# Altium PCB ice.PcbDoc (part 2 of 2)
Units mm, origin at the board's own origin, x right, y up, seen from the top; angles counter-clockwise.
Board outline 65 x 30 mm, 4 copper layers (L1 [TOP], L2 [GND], L3[PWR], L4 [BOTTOM]), stack 1.49 mm thick; 140 components, 110 nets, 478 pads, 226 vias.
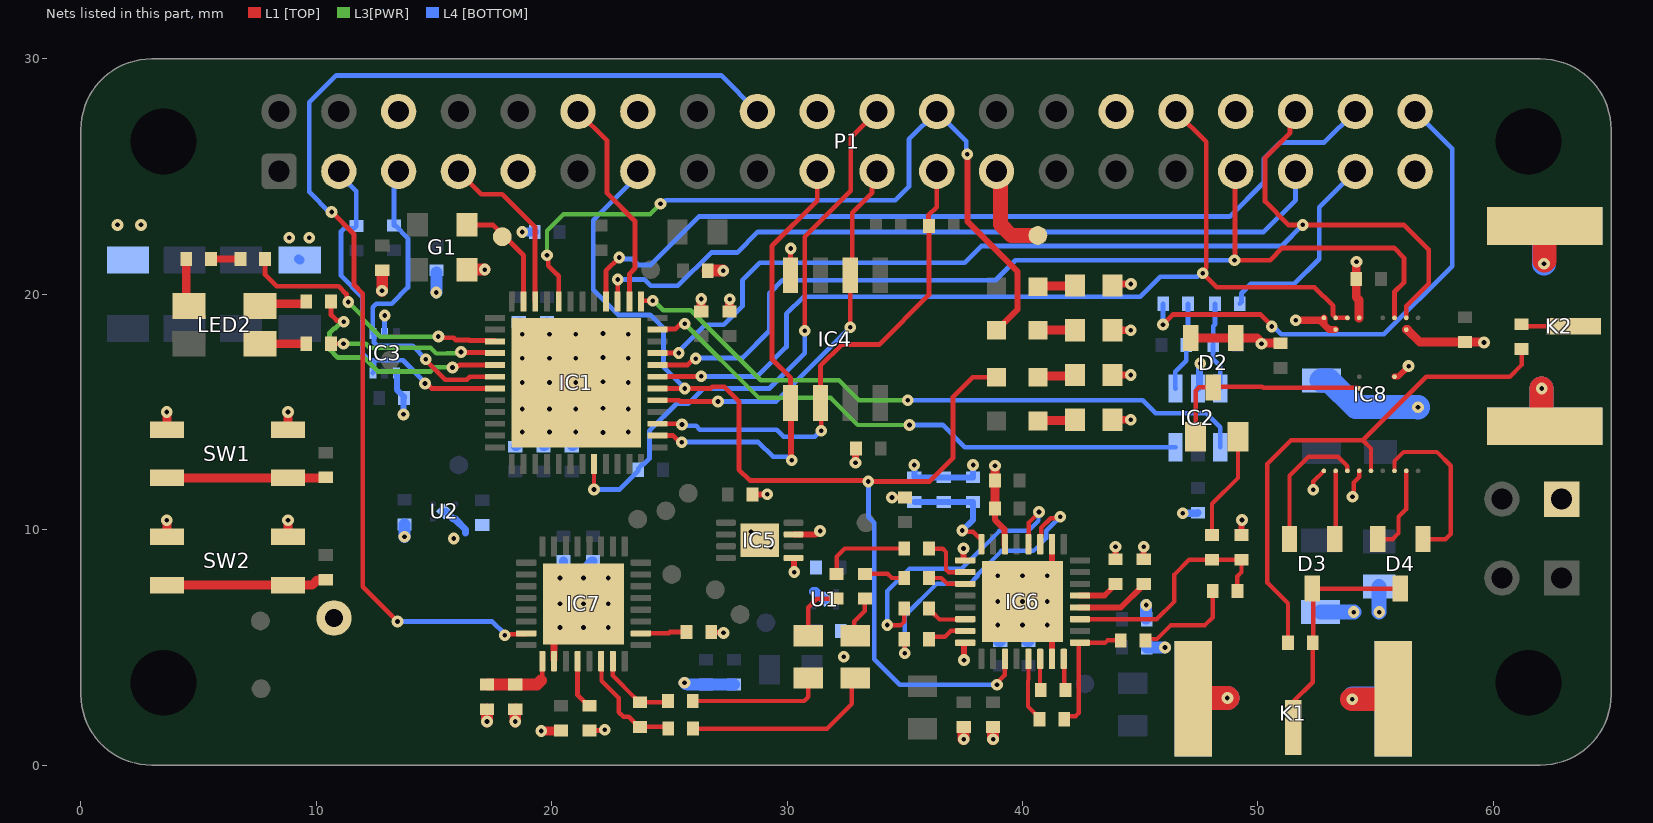
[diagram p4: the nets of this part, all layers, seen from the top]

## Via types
v1: diameter 0.5, hole 0.2, L1 [TOP] to L4 [BOTTOM], tented both sides, 226 vias

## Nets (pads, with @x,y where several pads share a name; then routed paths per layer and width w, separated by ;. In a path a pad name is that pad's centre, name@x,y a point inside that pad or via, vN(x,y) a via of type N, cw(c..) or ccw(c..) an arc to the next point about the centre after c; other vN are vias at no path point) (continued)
F_MISO: IC1.17 IC4.2 P1.21 | length 16.6
  L1 [TOP] w0.203: IC1.17@24.5,15.5 25.416,15.5 25.471,15.445 v1(27.061,15.445) ; v1(32.677,18.597) 32.677,20.75 32.762,20.835 32.762,23.462 33.609,24.309 33.609,25.019 P1.21@33.815,25.225
  L4 [BOTTOM] w0.203: v1(27.061,15.445) 29.525,15.445 v1(32.677,18.597)
F_MOSI: IC1.14 IC4.5 P1.19 | length 22.4
  L1 [TOP] w0.203: IC1.14@24.5,14 25.163,14 25.446,13.717 v1(25.518,13.717) ; IC4.5@30.3,15.8 30.2,15.7 v1(30.2,12.95) 30.2,13.022 30.145,13.077 30.145,16.455 29.357,17.243 29.357,22.057 31.275,23.975 P1.19@31.275,25.225
  L4 [BOTTOM] w0.203: v1(25.518,13.717) 25.526,13.725 28.775,13.725 29.4,13.1 v1@30.2,13.1
F_SCLK: IC1.15 IC4.6 P1.23 R14.2 | length 21.3
  L1 [TOP] w0.203: IC1.15@24.5,14.5 24.505,14.505 25.501,14.505 v1(25.535,14.471) ; v1(31.45,14.2) 31.45,15.353 IC4.6@31.415,15.388 31.415,16.965 32.317,17.867 33.917,17.867 36.025,19.975 36.025,22.75 36,22.775 36,23.35 36.355,23.705 P1.23@36.355,25.225
  L4 [BOTTOM] w0.203: v1(25.535,14.471) 25.592,14.414 26.129,14.414 26.293,14.25 29.55,14.25 29.85,13.95 31.182,13.95 31.432,14.2 v1(31.45,14.2)
GND: C1.1 C2.1 C3.1 C4.1 C5.1 C6.1 C7.1 C8.1 C9.1 C10.1 C11.1 C12.1 C13.1 C14.1 C15.2 C16.2 C17.1 C18.2 C19.1 C20.1 C28.2 C29.2 C30.2 C31.2 C32.2 C33.1 C34.1 C35.2 C36.1 C37.1 C38.1 C39.1 C40.1 C41.1 C42.1 C43.1 C44.1 C45.1 C48.1 C49.1 C50.1 C51.1 C52.1 C53.1 C54.2 C55.2 C56.1 C57.1 C58.1 C59.1 D2.1 D2.2 G1.2 IC1.49 IC2.2 IC3.2 IC3.4 IC4.4 IC5.5 IC5.7 IC5.9 IC6.10 IC6.14 IC6.17 IC6.24 IC6.31 IC6.33 IC7.26 IC7.33 IC8.A1 IC8.A4 IC8.B2 IC8.B8 IC8.F7 IC8.P1 IC8.P4 K1.2 K2.2 K4.1 LED1.1 LED3.1 LED4.1 LED5.1 P1.6 P1.9 P1.14 P1.20 P1.25 P1.30 P1.34 P1.39 R16.2 R24.1 SW1.3 SW1.4 SW2.3 SW2.4 TP20.1 TP27.1 U1.2 U1.5 U2.2 U2.5 | length 95.5
  L1 [TOP] w0.185: v1@8.8,10.35 v1(8.8,10.4) ; v1(52.35,11.7) 52.35,12.05 IC8.P1@52.8,12.5 ; v1(54.019,11.4) 54.066,11.447 54.066,12.007 54.3,12.241 IC8.P4@54.3,12.5
  L1 [TOP] w0.203: R16.2@21.6,1.475 22.225,1.475 v1(22.25,1.5) ; C31.2@26.775,5.65 26.791,5.634 27.284,5.634 v1(27.3,5.618) ; IC4.4@30.145,20.812 30.145,21.845 30.15,21.85 v1(30.15,21.95)
  L1 [TOP] w0.254: C1.1@27.55,19.275 C1.1@27.554,19.279 ; v1@27.554,19.791 v1(27.557,19.795) ; C17.1@28.525,11.5 29.14,11.5 v1(29.15,11.51) ; IC5.5@30.27,8.8 30.292,8.8 30.3,8.792 v1(30.3,8.2) ; IC5.7@30.27,9.8 30.559,9.8 30.563,9.804 31.198,9.804 31.344,9.95 v1(31.4,9.95) ; v1(34.45,11.366) 34.455,11.37 34.995,11.37 C41.1@35,11.375 ; v1(37.494,9.202) 37.494,8.728 37.52,8.703 IC6.17@37.612,8.703 ; v1(37.511,4.461) 37.511,5.172 37.536,5.197 IC6.24@37.612,5.197 ; C39.1@38.824,10.895 38.824,10.426 39.227,10.023 39.227,9.348 IC6.14@39.238,9.338 ; v1@38.825,12.716 v1(38.826,12.717) ; IC6.31@41.245,4.562 41.245,5.705 v1(40,6.95) 41.245,8.195 IC6.10@41.245,9.338 ; C30.2@43.95,8.75 v1(43.95,9.275) ; v1(45.145,9.276) 45.148,9.273 45.148,8.752 C29.2@45.15,8.75 ; C28.2@49.3,9.775 49.3,10.393 v1(49.318,10.411) ; IC8.F7@55.8,16.5 55.95,16.5 v1(56.4,16.95) ; C40.1@38.824,12.095 C40.1@38.825,12.096
  L1 [TOP] w0.3: IC7.26@20.105,4.462 IC7.33@20.105,5.605
  L1 [TOP] w0.305: IC7.33@20.105,5.605 v1(21.35,6.85) ; v1(32.9,12.85) 32.9,13.425 C16.2@32.925,13.45 ; LED5.1@43.825,14.675 v1(44.6,14.675) ; LED4.1@43.825,16.575 v1(44.6,16.575) ; LED3.1@43.825,18.475 v1(44.6,18.475) ; LED1.1@43.825,20.375 43.892,20.442 v1(44.602,20.442) ; v1(51.6,18.9) 52.623,18.9 52.8,18.723 ; IC8.A1@52.8,19 52.8,18.723 ; IC8.B2@53.3,18.5 53.023,18.5 52.8,18.723
  L1 [TOP] w0.381: SW2.3@3.65,9.7 v1(3.65,10.4) ; SW1.3@3.65,14.25 v1(3.65,15) ; SW2.4@8.8,9.7 v1@8.8,10.35 ; SW1.4@8.8,14.25 v1(8.8,15) ; v1(19.55,1.45) 20.375,1.45 C18.2@20.4,1.475 ; C2.1@26.35,19.23 v1(26.35,19.8) ; C1.1@27.554,19.279 v1@27.554,19.791 ; C39.1@38.824,10.895 C40.1@38.824,12.095 v1@38.825,12.716 ; D2.2@47.14,18.15 D2.1@49.06,18.15 49.958,18.15 v1@50.208,17.9 ; v1(50.15,17.9) v1@50.208,17.9 ; C36.1@50.95,17.925 50.275,17.925 50.25,17.9 v1@50.208,17.9 ; v1(54.185,21.383) 54.175,21.372 C32.2@54.175,20.65 54.175,19.875 54.3,19.75 IC8.A4@54.3,19 ; IC8.B8@56.3,18.5 56.35,18.5 56.875,17.975 C35.2@58.8,17.975 59.525,17.975 59.55,17.95 v1(59.6,17.95)
  L1 [TOP] w0.508: v1(12.786,20.149) 12.8,20.163 C56.1@12.8,20.918 ; G1.2@16.4,21.05 v1(17.15,21.05) ; v1(17.25,1.85) C20.1@17.25,2.375 ; v1(18.45,1.85) C19.1@18.45,2.375 ; C9.1@26.625,21 26.629,21.004 v1(27.286,21.004) ; v1(28.465,9.92) IC5.9@28.835,9.55 ; v1(37.5,1.1) C50.1@37.5,1.625 ; v1(38.75,1.1) C51.1@38.75,1.625 ; K1.2@55.725,2.8 K1.2@55.75,2.825 ; K2.2@62.05,14.525 K2.2@62.175,14.4 ; v1(62.15,21.3) 62.15,21.4 v1@62.175,21.425
  L1 [TOP] w0.635: P1.25@38.895,25.225 39.06,25.06 39.06,22.965 39.525,22.5 TP27.1@40.65,22.5
  L1 [TOP] w1.016: K1.2@47.275,2.85 v1(48.7,2.85) ; v1(54,2.8) K1.2@55.725,2.8 ; K2.2@62.05,14.525 v1(62.05,16) ; v1@62.175,21.425 K2.2@62.175,22.9
  L1 [TOP] w1.27: K1.2@47.25,2.825 K1.2@47.275,2.85
  L4 [BOTTOM] w0.203: IC3.2@12.9,18.338 12.902,18.34 v1(12.904,19.096) v1(12.904,19.096) ; C8.1@19.275,22.65 C8.1@19.278,22.647
  L4 [BOTTOM] w0.254: IC3.4@13.4,16.662 13.4,16.575 13.423,16.552 13.423,15.952 13.725,15.65 C15.2@13.725,15.6 13.713,15.587 13.713,14.913 v1(13.7,14.9) ; v1(35.4,12.75) C48.1@35.4,12.225 C49.1@36.65,12.225 R24.1@37.9,12.225 v1(37.9,12.75) ; C53.1@45.25,6.225 C53.1@45.275,6.2 ; C52.1@45.275,5 C52.1@45.277,4.998
  L4 [BOTTOM] w0.305: U2.5@15.425,10.775 15.502,10.775 15.827,10.45 U2.2@15.9,10.45 ; U2.2@15.905,10.45 U2.2@15.9,10.45 ; 16.341,9.87 16.341,10.009 U2.2@15.9,10.45 ; v1(46.8,10.7) 47.425,10.7 C14.1@47.45,10.725 ; IC2.2@47.45,16 47.514,16.064 47.514,17.034 v1(47.544,17.064)
  L4 [BOTTOM] w0.381: C58.1@9.25,21.5 C58.1@9.3,21.45 ; C3.1@18.45,13.525 18.5,13.525 18.559,13.584 18.559,13.938 18.75,14.129 v1(18.75,14.15) ; C6.1@18.6,18.825 18.65,18.825 18.71,18.766 18.71,18.362 18.75,18.321 v1(18.75,18.3) ; v1(18.75,22.65) C8.1@19.275,22.65 ; C4.1@19.65,13.525 19.7,13.525 19.759,13.584 19.759,13.988 19.9,14.129 v1(19.901,14.15) ; v1@19.774,18.3 19.787,18.313 19.787,18.812 C5.1@19.8,18.825 ; v1(20.35,7.95) 20.35,8 20.5,8.15 C42.1@20.5,8.675 ; C7.1@20.85,13.525 20.9,13.525 20.959,13.584 20.959,14.066 21.022,14.129 v1(21.022,14.15) ; v1(21.35,7.95) 21.392,7.992 21.392,8.367 21.7,8.675 C43.1@21.75,8.675 ; U1.2@31.126,7.371 31.206,7.371 31.531,7.046 U1.5@31.601,7.046
  L4 [BOTTOM] w0.508: v1(13.75,9.7) C12.1@13.75,10.225 ; v1(15.096,20.074) 15.098,20.077 15.098,20.928 C57.1@15.1,20.93 ; v1(25.639,3.5) 25.689,3.45 25.75,3.45 25.775,3.425 C33.1@26.55,3.425 C34.1@27.75,3.425 ; v1(38.95,5.95) 39.004,5.896 39.004,5.279 39.008,5.275 C37.1@39.05,5.275 ; v1(40,5.95) 40.204,5.746 40.204,5.279 40.208,5.275 C38.1@40.25,5.275 ; C53.1@45.25,6.225 v1(45.25,6.8) ; C52.1@45.277,4.998 45.279,5 v1(46.05,5) ; v1(54,2.8) v1@54.025,2.825 ; K2.2@62.05,14.525 K2.2@62.175,14.4 ; K2.2@62.15,22.875 K2.2@62.175,22.9
  L4 [BOTTOM] w0.635: C45.1@52.65,6.5 v1(54.071,6.5) ; v1(55.15,6.5) C44.1@55.15,7.595
  L4 [BOTTOM] w1.016: K1.2@47.25,2.825 47.275,2.85 v1(48.7,2.85) ; C55.2@52.7,16.348 53.017,16.348 54.16,15.205 C54.2@55.2,15.205 56.795,15.205 v1(56.8,15.2) ; v1@54.025,2.825 K1.2@55.75,2.825 ; K2.2@62.05,14.525 v1(62.05,16) ; v1(62.15,21.3) K2.2@62.15,22.875
  other v1: 32.4,4.6 20.35,5.85 21.35,5.85 22.4,5.85 41.05,5.95 20.35,6.85 22.4,6.85 38.95,6.95 41.05,6.95 22.4,7.95 38.95,8.05 40,8.05 41.05,8.05 29.3,9.25 15.837,9.627 22.175,14.132 23.25,14.15 18.75,15.128 19.901,15.128 21.022,15.128 23.25,15.128 22.175,15.16 18.75,16.25 19.901,16.25 21.022,16.25 23.25,16.25 22.175,16.282 18.75,17.286 19.901,17.286 21.022,17.286 23.25,17.286 22.175,17.318 19.901,18.3 21.022,18.3 23.25,18.3 22.175,18.332 8.85,22.4 9.7,22.4 1.55,22.95 2.55,22.95
HILO: IC1.18 IC6.27 P1.13 R10.1 | length 48.5
  L1 [TOP] w0.185: P1.13@23.655,24.869 P1.13@23.655,25.225 ; v1(38.914,3.413) 38.914,3.499 39.238,3.823 IC6.27@39.238,4.562
  L1 [TOP] w0.203: IC1.18@24.5,16 v1(25.651,15.999) ; v1@25.65,16.001 25.651,16.003 26.745,16.003 26.814,16.071 27.337,16.071 27.95,15.458 27.95,12.55 28.408,12.092 33.408,12.092 v1(33.45,12.05) 36.05,12.05 37.05,13.05 37.05,15.65 37.875,16.475 R10.1@38.9,16.475
  L4 [BOTTOM] w0.203: P1.13@23.655,25.225 23.655,25.031 21.762,23.137 21.762,20.188 22.825,19.125 24.175,19.125 24.75,18.55 24.75,16.904 25.651,16.003 v1(25.651,15.999) ; v1(33.45,12.05) 33.45,10.55 33.7,10.3 33.7,4.5 34.787,3.413 v1(38.914,3.413)
HV_EN: IC1.34 P1.7 | length 7.4
  L1 [TOP] w0.203: P1.7@16.035,25.225 17.01,24.25 17.9,24.25 19.293,22.857 19.293,19.707 IC1.34@19.3,19.7
ICE_CS: IC1.32 P1.24 R8.1 | length 34.1
  L1 [TOP] w0.203: v1(19.8,21.662) 19.857,21.606 19.857,21.222 20.26,20.818 20.26,20.815 20.3,20.776 IC1.32@20.3,19.7
  L1 [TOP] w0.254: v1(37.65,25.95) 37.652,25.948 37.652,23.098 39.775,20.975 39.775,19.35 R8.1@38.9,18.475
  L3[PWR] w0.185: v1(19.8,21.662) 19.8,22.7 20.5,23.4 24.178,23.4 v1(24.624,23.847)
  L4 [BOTTOM] w0.203: v1(24.624,23.847) 24.699,23.847 24.852,24 34.6,24 35.175,24.575 35.175,26.585 P1.24@36.355,27.765 37.611,26.509 37.611,25.989 v1(37.65,25.95)
Lblue: IC1.41 R5.2 | length 10.3
  L1 [TOP] w0.203: R5.2@10.625,19.7 10.625,19.125 10.858,18.892 11.108,18.892 v1(11.165,18.835) ; v1(15.784,16.891) 15.841,16.948 16.028,16.948 16.082,17.002 17.598,17.002 IC1.41@17.6,17
  L3[PWR] w0.203: v1(11.165,18.835) 11.084,18.835 10.812,18.563 10.764,18.563 10.564,18.364 10.564,17.657 10.907,17.314 12.036,17.314 12.63,16.72 14.848,16.72 15.026,16.898 15.777,16.898 v1(15.784,16.891)
Lgreen: IC1.40 R7.2 | length 7.2
  L1 [TOP] w0.203: R7.2@10.625,17.9 v1(11.15,17.9) ; v1(16.15,17.55) 16.177,17.523 17.577,17.523 IC1.40@17.6,17.5
  L3[PWR] w0.185: v1(11.15,17.9) 12.1,17.9 12.268,17.732 14.855,17.732 15.097,17.489 15.542,17.489 ; 15.543,17.49 16.09,17.49 v1(16.15,17.55)
Lred: IC1.39 R2.2 | length 11.8
  L1 [TOP] w0.203: R2.2@7.825,21.5 7.825,20.831 8.313,20.342 10.946,20.342 11.276,20.012 11.276,19.948 11.306,19.918 11.306,19.723 v1(11.359,19.67) ; v1(15.185,18.209) 15.242,18.153 15.83,18.153 15.923,18.059 16.481,18.059 16.497,18.044 16.975,18.044 16.986,18.033 17.567,18.033 IC1.39@17.6,18
  L3[PWR] w0.185: v1(11.359,19.67) 11.956,19.073 11.956,18.959 12.715,18.2 15.176,18.2 v1(15.185,18.209)
NetC19_2: C19.2 C20.2 IC7.25 | length 3.2
  L1 [TOP] w0.203: 19.55,3.65 19.597,3.697 IC7.25@19.597,4.462
  L1 [TOP] w0.508: C20.2@17.25,3.425 C19.2@18.45,3.425 19.37,3.425 19.55,3.605
NetC21_1: C21.1 IC6.30 | length 1.4
  L1 [TOP] w0.185: C21.1@40.725,3.2 40.744,3.219 40.744,4.544 IC6.30@40.762,4.562
NetC21_2: C21.2 IC6.32 | length 1.4
  L1 [TOP] w0.185: IC6.32@41.753,4.562 41.764,4.551 41.764,3.211 C21.2@41.775,3.2
NetC22_1: C22.1 IC6.1 R17.2 | length 5.5
  L1 [TOP] w0.185: C22.1@41.775,1.95 41.908,2.083 42.252,2.083 42.388,2.218 42.388,5.197 43.505,5.197 43.608,5.3 R17.2@44.175,5.3
NetC22_2: C22.2 IC6.29 | length 2.8
  L1 [TOP] w0.185: IC6.29@40.25,4.515 40.254,4.511 40.254,3.625 40.23,3.601 40.23,2.495 40.725,2 C22.2@40.725,1.95
NetC23_1: C23.1 C25.1 C28.1 IC6.3 | length 10
  L1 [TOP] w0.185: IC6.3@42.395,6.195 45.695,6.195 46.45,6.95 46.45,8.1 47.075,8.725 C25.1@48.05,8.725 49.258,8.725 C28.1@49.3,8.725 49.3,8.2 49.125,8.025 C23.1@49.125,7.4
NetC23_2: C23.2 R17.1 | length 4.4
  L1 [TOP] w0.185: R17.1@45.225,5.3 45.284,5.359 45.709,5.359 46.3,5.95 47.75,5.95 48.075,6.275 C23.2@48.075,7.4
NetC24_1: C24.1 IC7.30 R18.2 | length 4.9
  L1 [TOP] w0.185: IC7.30@22.112,4.462 22.112,3.588 22.85,2.85 22.85,2.25 23.046,2.054 23.271,2.054 23.7,1.625 C24.1@23.75,1.625 24.875,1.625 R18.2@24.95,1.55
NetC24_2: C24.2 IC7.31 R15.2 | length 3.5
  L1 [TOP] w0.185: IC7.31@22.595,4.462 22.595,3.805 23.542,2.858 23.542,2.833 23.7,2.675 C24.2@23.75,2.675 24.89,2.675 R15.2@24.942,2.727
NetC25_2: C25.2 L3.2 | length 4.6
  L1 [TOP] w0.185: C25.2@48.05,9.775 48.05,11.1 49.15,12.2 L3.2@49.15,13.95
NetC26_1: C26.1 L1.1 | length 2.6
  L1 [TOP] w0.185: L1.1@30.9,5.5 30.9,6.7 31.275,7.075 C26.1@32.1,7.075
NetC26_2: C26.2 R19.2 | length 3.7
  L1 [TOP] w0.185: C26.2@32.1,8.125 32.1,8.85 32.45,9.2 R19.2@34.975,9.2
NetC27_1: C27.1 L2.1 | length 1.8
  L1 [TOP] w0.185: L2.1@32.9,5.5 32.85,5.55 32.85,6.1 33.3,6.55 C27.1@33.3,7.075
NetC27_2: C27.2 R20.2 | length 1.7
  L1 [TOP] w0.185: C27.2@33.3,8.125 34.275,8.125 34.45,7.95 R20.2@34.975,7.95
NetC29_1: C29.1 IC6.4 | length 3.1
  L1 [TOP] w0.254: IC6.4@42.388,6.696 44.171,6.696 C29.1@45.1,7.625
NetC30_1: C30.1 IC6.5 | length 1.8
  L1 [TOP] w0.254: IC6.5@42.388,7.204 43.479,7.204 43.95,7.675 C30.1@44,7.675
NetC31_1: C31.1 IC7.2 | length 2
  L1 [TOP] w0.185: IC7.2@23.738,5.605 24.537,5.605 24.543,5.6 24.957,5.6 24.963,5.605 24.98,5.605
  L1 [TOP] w0.203: 24.98,5.605 25.025,5.65 C31.1@25.725,5.65
NetC46_1: C46.1 IC6.11 | length 12.2
  L1 [TOP] w0.185: C46.1@34.975,5.35 35,5.325 v1(35,4.75) ; IC6.11@40.762,9.697 40.788,9.723 40.788,10.08 41.197,10.49 41.54,10.49 v1(41.6,10.55)
  L4 [BOTTOM] w0.185: v1(35,4.75) 35,6.35 36.35,7.7 37.75,7.7 38.1,8.05 38.1,8.1 39.1,9.1 40.461,9.1 41.004,9.643 41.004,9.954 v1(41.6,10.55)
NetC46_2: C46.2 IC6.23 | length 1.7
  L1 [TOP] w0.185: C46.2@36.025,5.45 36.7,5.45 36.955,5.705 IC6.23@37.612,5.705
NetC47_1: C47.1 IC6.12 | length 12.4
  L1 [TOP] w0.185: v1(34.25,5.95) 34.832,5.95 34.968,6.085 34.968,6.643 C47.1@34.975,6.65 ; IC6.12@40.288,9.371 40.268,9.391 40.268,10.306 40.7,10.737 v1(40.7,10.75)
  L4 [BOTTOM] w0.185: v1(34.25,5.95) 34.25,7.4 35.2,8.35 37.416,8.35 39.016,9.95 40.244,9.95 40.679,10.385 40.679,10.729 v1(40.7,10.75)
NetC47_2: C47.2 IC6.22 | length 1.8
  L1 [TOP] w0.185: C47.2@36.025,6.7 36.183,6.542 36.183,6.477 36.472,6.188 IC6.22@37.612,6.188
NetC48_2: C48.2 C49.2 IC6.16 R24.2 | length 5.1
  L1 [TOP] w0.185: v1(37.442,9.966) 37.494,9.913 37.896,9.913 38.157,9.652 38.187,9.652 38.247,9.592 IC6.16@38.247,9.338
  L4 [BOTTOM] w0.254: C48.2@35.4,11.175 C49.2@36.65,11.175 R24.2@37.9,11.175 37.9,10.424 v1(37.442,9.966)
NetD2_3: D2.3 IC8.G4 L3.1 | length 9
  L1 [TOP] w0.185: L3.1@47.35,13.95 47.362,13.963 47.362,15.915 47.498,16.05 D2.3@48.1,16.05 48.125,16.075 50.175,16.075 50.225,16.025 54.209,16.025 54.232,16.003 54.297,16.003 IC8.G4@54.3,16
NetD3_1: D3.1 IC8.P2 | length 2.9
  L1 [TOP] w0.185: D3.1@53.26,9.6 53.3,9.64 IC8.P2@53.3,12.5
NetD3_2: D3.2 IC8.P3 | length 5.9
  L1 [TOP] w0.185: D3.2@51.34,9.6 51.34,12.29 52.15,13.1 53.4,13.1 53.797,12.703 53.797,12.503 IC8.P3@53.8,12.5
NetD3_3: D3.3 D4.3 K1.1 R22.1 | length 10.6
  L1 [TOP] w0.185: K1.1@51.5,1 51.5,2.7 52.325,3.525 R22.1@52.325,5.2 52.35,5.225 52.35,7.45 D3.3@52.3,7.5 D4.3@56.05,7.5
NetD4_1: D4.1 IC8.P7 | length 7.4
  L1 [TOP] w0.185: IC8.P7@55.8,12.5 55.8,12.915 56.185,13.3 57.6,13.3 58.185,12.715 58.185,9.82 57.965,9.6 D4.1@57.01,9.6
NetD4_2: D4.2 IC8.P8 | length 3.8
  L1 [TOP] w0.185: D4.2@55.09,9.6 55.714,9.6 55.97,9.856 55.97,10.548 56.3,10.877 IC8.P8@56.3,12.5
NetIC2_1: IC2.1 R30.2 R31.2 | length 3.6
  L4 [BOTTOM] w0.203: IC2.1@46.5,16 46.49,16.01 46.49,16.719 46.95,17.179 R30.2@46.95,17.65 ; R30.2@46.95,17.85 46.95,18.6 47.025,18.675 R31.2@47.025,19.6
NetIC2_3: IC2.3 R29.2 R32.2 | length 3.8
  L4 [BOTTOM] w0.203: R32.2@48.175,19.6 48.175,18.725 48.1,18.65 R29.2@48.1,17.85 48.084,17.834 48.084,17.266 48.4,16.95 IC2.3@48.4,16
NetIC7_28: IC7.28 R16.1 | length 2.2
  L1 [TOP] w0.185: IC7.28@21.096,4.361 IC7.28@21.096,4.462
  L1 [TOP] w0.203: IC7.28@21.096,4.361 21.096,2.979 21.55,2.525 R16.1@21.6,2.525
NetK2_1: K2.1 R23.2 | length 2.6
  L1 [TOP] w0.185: R23.2@61.2,18.725 61.275,18.65 K2.1@63.75,18.65
NetL1_2: L1.2 R15.1 | length 5.8
  L1 [TOP] w0.185: R15.1@25.992,2.727 30.727,2.727 30.9,2.9 L1.2@30.9,3.7
NetL2_2: L2.2 R18.1 | length 8.3
  L1 [TOP] w0.185: R18.1@26,1.55 31.693,1.55 32.75,2.607 32.75,3.55 L2.2@32.9,3.7
NetLED1_2: LED1.2 R4.2 | length 1.6
  L1 [TOP] w0.381: R4.2@40.65,20.325 40.675,20.35 42.2,20.35 LED1.2@42.225,20.375
NetLED2_1: LED2.1 R1.1 | length 2.1
  L1 [TOP] w0.381: R1.1@4.475,21.5 4.475,19.625 LED2.1@4.6,19.5
NetLED2_3: LED2.3 R5.1 | length 2.1
  L1 [TOP] w0.381: LED2.3@7.6,19.5 7.7,19.6 9.516,19.6 9.575,19.66 R5.1@9.575,19.7
NetLED2_4: LED2.4 R7.1 | length 2
  L1 [TOP] w0.381: LED2.4@7.6,17.9 R7.1@9.575,17.9
NetLED3_2: LED3.2 R8.2 | length 1.6
  L1 [TOP] w0.381: R8.2@40.65,18.475 LED3.2@42.225,18.475
NetLED4_2: LED4.2 R10.2 | length 1.6
  L1 [TOP] w0.381: R10.2@40.65,16.475 40.7,16.525 42.175,16.525 LED4.2@42.225,16.575
NetLED5_2: LED5.2 R9.2 | length 1.6
  L1 [TOP] w0.381: R9.2@40.65,14.625 40.675,14.65 42.2,14.65 LED5.2@42.225,14.675
NetR1_2: R1.2 R2.1 | length 1.3
  L1 [TOP] w0.305: R1.2@5.525,21.5 R2.1@6.775,21.5
NetR21_1: R21.1 SW2.1 SW2.2 | length 6.8
  L1 [TOP] w0.381: SW2.1@3.65,7.65 SW2.2@8.8,7.65 9.82,7.65 10.045,7.875 R21.1@10.4,7.875
NetR26_1: R26.1 SW1.1 SW1.2 | length 7
  L1 [TOP] w0.381: SW1.1@3.65,12.2 SW1.2@8.8,12.2 ; SW1.2@8.55,12.2 10.375,12.2 R26.1@10.4,12.225
OutRange: IC7.23 P1.18 | length 49.6
  L1 [TOP] w0.185: v1(18,5.514) 18.046,5.56 18.916,5.56 IC7.23@18.962,5.605
  L1 [TOP] w0.203: v1(10.65,23.5) 11.6,22.55 11.6,20.4 11.976,20.024 11.976,7.574 v1(13.45,6.1)
  L4 [BOTTOM] w0.203: v1@10.6,23.45 9.7,24.35 9.7,28.15 10.85,29.3 27.2,29.3 P1.18@28.735,27.765 ; v1(13.45,6.1) 17.474,6.1 18,5.574 v1(18,5.514)
PCM_CLK: IC1.26 P1.12 | length 9.2
  L1 [TOP] w0.203: P1.12@21.115,27.765 22.35,26.53 22.35,24.3 23.537,23.113 23.537,21.107 23.308,20.878 23.308,20.423 23.3,20.415 IC1.26@23.3,19.7
PCM_DIN: IC1.28 P1.38 | length 36.8
  L1 [TOP] w0.203: IC1.28@22.3,19.7 22.3,20.998 v1(22.864,21.562)
  L4 [BOTTOM] w0.203: v1(22.864,21.562) 22.92,21.505 23.409,21.505 23.664,21.25 24.2,21.25 26.25,23.3 48.8,23.3 50.25,24.75 50.25,25.75 50.95,26.45 52.82,26.45 P1.38@54.135,27.765
PCM_FS: IC1.27 P1.35 | length 32.6
  L1 [TOP] w0.185: IC1.27@22.8,19.7 22.802,19.702 22.802,20.629 v1(22.804,20.631)
  L4 [BOTTOM] w0.203: v1(22.804,20.631) 23.933,20.631 24.205,20.36 25.36,20.36 26.775,21.775 27.875,21.775 28.75,22.65 50.25,22.65 51.595,23.995 P1.35@51.595,25.225
Pdamp: IC1.19 IC8.A2 IC8.A3 P1.32 | length 40.4
  L1 [TOP] w0.203: IC1.19@24.5,16.5 24.508,16.508 26.344,16.508 v1(26.352,16.515) ; P1.32@46.515,27.765 47.8,26.48 47.8,21.13 47.65,20.98 v1(47.65,20.9) 48.25,20.3 52.4,20.3 53.192,19.508 53.192,19.112 53.3,19.004 IC8.A2@53.3,19 53.303,19.003 53.368,19.003 53.369,19.004 53.792,19.004 53.796,19 IC8.A3@53.8,19
  L4 [BOTTOM] w0.203: v1(26.352,16.515) 26.362,16.505 28.705,16.505 29.966,17.767 29.966,19.167 30.7,19.9 45,19.9 45.85,20.75 47.425,20.75 47.575,20.9 v1(47.65,20.9)
PHV: IC1.21 IC8.A8 P1.36 | length 45.8
  L1 [TOP] w0.203: IC1.21@24.5,17.5 24.502,17.502 25.398,17.502 v1(25.4,17.504) ; P1.36@51.595,27.765 51.366,27.536 51.366,26.866 50.3,25.8 50.3,23.945 51.295,22.95 v1(51.9,22.95) 56.2,22.95 57.25,21.9 57.25,20.45 56.3,19.5 IC8.A8@56.3,19
  L4 [BOTTOM] w0.203: v1(25.4,17.504) 25.4,17.576 26.527,18.703 27.303,18.703 28.1,19.5 28.1,20.6 28.844,21.344 37.544,21.344 38.25,22.05 51,22.05 v1(51.9,22.95)
PnHV: IC1.20 IC8.A7 P1.33 | length 41.4
  L1 [TOP] w0.203: IC1.20@24.5,17 25.769,17 26.038,17.268 v1(26.118,17.268) ; P1.33@49.055,25.225 49.027,25.198 49.027,21.477 v1(49,21.45) 50.515,21.45 51.035,21.97 55.78,21.97 56.2,21.55 56.2,20.5 55.8,20.1 IC8.A7@55.8,19
  L4 [BOTTOM] w0.203: v1(26.118,17.268) 26.14,17.29 28.09,17.29 29.25,18.45 29.25,20.05 29.8,20.6 38.85,20.6 39.7,21.45 v1(49,21.45)
RCLK: G1.3 IC1.35 TP6.1 | length 4.9
  L1 [TOP] w0.203: G1.3@16.4,22.95 17.5,22.95 18.8,21.65 IC1.35@18.8,19.7
RESET: IC1.8 P1.22 R3.2 | length 24.7
  L1 [TOP] w0.185: v1(21.794,11.709) 21.797,11.712 21.797,12.797 IC1.8@21.8,12.8
  L1 [TOP] w0.203: v1(30.75,18.45) 30.75,22.45 32.7,24.4 32.7,26.65 P1.22@33.815,27.765
  L4 [BOTTOM] w0.203: v1(21.794,11.709) v1(21.794,11.709) 22.885,11.71 23.675,12.5 23.675,12.6 23.833,12.758 23.883,12.758 24.15,13.025 24.15,14.2 25.3,15.35 25.8,15.35 26.45,16 29.25,16 30.75,17.5 v1(30.75,18.45)
SCL: IC1.42 IC3.1 P1.5 R12.2 | length 14.6
  L1 [TOP] w0.203: v1(14.65,17.237) 14.65,17.199 15.478,16.371 16.4,16.371 16.528,16.5 IC1.42@17.6,16.5
  L4 [BOTTOM] w0.203: IC3.1@12.4,18.338 IC3.1@12.4,18.396 ; P1.5@13.495,25.225 13.3,25.03 13.3,23.9 R12.2@13.3,22.925 13.35,22.925 13.892,22.383 13.892,20.292 13.2,19.6 12.549,19.6 12.4,19.451 IC3.1@12.4,18.396 ; v1(14.65,17.237) 14.65,17.25 14.092,17.808 12.589,17.808 12.454,17.943 12.454,18.342 IC3.1@12.4,18.396
SDA: IC1.43 IC3.6 P1.3 R11.2 | length 15.8
  L1 [TOP] w0.203: v1(14.614,16.21) 14.694,16.21 14.904,16 IC1.43@17.6,16
  L4 [BOTTOM] w0.203: P1.3@10.955,25.225 10.955,25.132 11.7,24.387 R11.2@11.7,22.9 11.604,22.804 11.185,22.804 11.05,22.669 11.05,20.794 11.958,19.887 11.958,17.5 12.258,17.2 12.455,17.2 13.682,17.2 14.614,16.268 v1(14.614,16.21) ; IC3.6@12.4,16.662 12.455,16.717 12.455,17.198 12.457,17.2
TOP_T1: IC1.23 IC2.6 | length 24.3
  L1 [TOP] w0.203: IC1.23@24.5,18.5 24.523,18.523 25.25,18.523 25.42,18.693 25.595,18.693 v1(25.652,18.75)
  L3[PWR] w0.185: v1(25.652,18.75) 28.802,15.6 31.85,15.6 33,14.45 v1(35.2,14.45)
  L4 [BOTTOM] w0.203: v1(35.2,14.45) 36.6,14.45 37.55,13.5 IC2.6@46.5,13.5
TOP_T1_in: P1.40 R31.1 | length 22.1
  L1 [TOP] w0.203: v1(45.963,18.713) 46.387,19.137 50.113,19.137 50.589,18.661 v1(50.589,18.631)
  L4 [BOTTOM] w0.185: R31.1@45.963,19.587 R31.1@45.975,19.6
  L4 [BOTTOM] w0.203: v1(45.963,18.713) R31.1@45.963,19.587 ; v1(50.589,18.631) 50.663,18.631 50.995,18.3 55.35,18.3 58.25,21.2 58.25,26.19 P1.40@56.675,27.765
TOP_T2: IC1.25 IC2.4 | length 27.7
  L1 [TOP] w0.203: IC1.25@23.8,19.7 23.828,19.728 v1(24.289,19.728)
  L3[PWR] w0.185: v1(24.289,19.728) 24.333,19.728 24.735,19.326 25.904,19.326 28.881,16.35 32.2,16.35 33.05,15.5 v1(35.122,15.5)
  L4 [BOTTOM] w0.203: v1(35.122,15.5) 45.1,15.5 45.65,14.95 47.804,14.95 48.4,14.354 IC2.4@48.4,13.5
TOP_T2_in: P1.37 R32.1 | length 8.7
  L4 [BOTTOM] w0.203: R32.1@49.225,19.6 49.3,19.675 49.3,20.05 49.7,20.45 51.55,20.45 52.6,21.5 52.6,23.69 P1.37@54.135,25.225
VOH2: IC6.18 R19.1 | length 2.4
  L1 [TOP] w0.185: R19.1@36.025,9.2 36.035,9.19 36.615,9.19 36.75,9.055 36.75,8.302 36.853,8.199 IC6.18@37.565,8.2
VOL2: IC6.19 R20.1 | length 1.7
  L1 [TOP] w0.185: R20.1@36.025,7.95 36.55,7.95 36.788,7.712 IC6.19@37.612,7.712
XDCR: IC8.P5 R22.2 R23.1 | length 22.6
  L1 [TOP] w0.185: R22.2@51.275,5.2 51.275,6.875 50.4,7.75 50.4,12.8 51.4,13.8 54.45,13.8 ; IC8.P5@54.8,12.5 54.8,13.45 54.45,13.8 ; R23.1@61.2,17.675 61.2,17 60.7,16.5 57.15,16.5 54.45,13.8
pads on no net: IC3.3 IC6.6 IC6.8 IC6.9 IC6.20 IC7.7 IC7.8 IC7.9 IC7.10 P1.11 P1.15 P1.17 P1.27 P1.28 P1.31

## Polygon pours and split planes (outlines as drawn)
+3V3_IN on L4 [BOTTOM] "+3V3_IN_L04_P022" (solid, pour order 22): 5.9,21.1 5.9,25.6 6.7,26.4 8.75,26.4 9.35,25.8 9.35,24.25 7.95,22.85 7.95,20.9 7.65,20.6 6.1,20.6 5.9,20.8
+1V2 on L4 [BOTTOM] "+1V2_L04_P036" (solid, pour order 36): 17.4,13.275 17.4,11.75 17.75,11.4 19.5,11.4 20.195,12.095 20.195,12.645 20.45,12.9 21.15,12.9 21.3,12.75 21.3,11.95 20.15,10.8 16.004,10.8 15.3,11.504 15.3,13.275
5VLNA on L4 [BOTTOM] "5VLNA_L04_P014" (solid, pour order 14): 45.25,3 45.213,2.963 42.012,2.963 41.764,3.211 41.764,4.014 42.75,5 42.75,8.5 43,8.75 44.25,8.75 44.75,8.25 44.75,4.75 45.25,4.25
+3V3 on L4 [BOTTOM] "+3V3_L04_P007" (solid, pour order 7): 13.356,11.884 13.39,11.85 14.81,11.85 15.04,11.619 15.04,10.967 13.356,10.967
+1V8 on L4 [BOTTOM] "+1V8_L04_P021" (solid, pour order 21): 30.2,5.25 30.1,5.35 28.65,5.35 28.4,5.6 28.4,6.6 28.65,6.85 31.2,6.85 31.6,6.45 31.6,3.5 31.35,3.25 30.428,3.25 30.201,3.476
+3V3 on L4 [BOTTOM] "+3V3_L04_P006" (solid, pour order 6): 31.75,8.4 31.75,7.421 32.1,7.071 32.1,6.55 32.6,6.55 33,6.95 33,8.45 32.8,8.65 32,8.65
GND on L4 [BOTTOM] "GND_L04_P029" (solid, pour order 29): 17.339,10.466 17.325,10.48 16.175,10.48 16.159,10.496 15.715,10.052 15.339,9.676 15.339,9.316 15.539,9.116 15.939,9.116 16.439,9.616 17.239,9.616 17.499,9.877 17.499,10.357
GND on L4 [BOTTOM] "GND_L04_P035" (solid, pour order 35): 20.05,8.25 22.75,8.25 22.75,5.5 20.05,5.5
GND on L4 [BOTTOM] "GND_L04_P034" (solid, pour order 34): 18.3,18.6 23.65,18.6 23.65,13.671 18.3,13.671
GND on L4 [BOTTOM] "GND_L04_P033" (solid, pour order 33): 8.4,20.8 10.3,20.8 10.3,22.45 9.95,22.8 8.7,22.8 8.4,22.5
GND on L4 [BOTTOM] "GND_L04_P032" (solid, pour order 32): 1.1,20.8 3,20.8 3,23.9 2.8,24.1 1.3,24.1 1.1,23.9
GND on L4 [BOTTOM] "GND_L04_P030" (solid, pour order 30): 32.85,6.05 32.85,4.35 32.7,4.2 32.15,4.2 31.95,4.4 31.95,6.05
GND on L4 [BOTTOM] "GND_L04_P008" (solid, pour order 8): 30,8.65 31.35,8.65 31.45,8.55 31.45,7.37 31.28,7.2 30.15,7.2 30,7.35
+5V_IN on L4 [BOTTOM] "+5V_IN_L04_P016" (solid, pour order 16): 3.5,20.8 5.4,20.8 5.4,23.9 5.2,24.1 3.7,24.1 3.5,23.9
+3V3 on L4 [BOTTOM] "+3V3_L04_P024" (solid, pour order 24): 5.9,19.2 5.9,17.75 6.05,17.6 6.05,15.9 6.3,15.65 8.65,15.65 10.2,15.65 10.45,15.9 10.45,19.1 10.15,19.4 6.05,19.4
+1V8f on L4 [BOTTOM] "+1V8F_L04_P003" (solid, pour order 3): 29.294,5.2 29.694,4.8 29.699,3.399 29.55,3.25 28.6,3.25 28.5,3.35 28.5,3.75 28.25,4 25.95,4 25.75,4.2 25.75,5 25.95,5.2
+5V on L4 [BOTTOM] "+5V_L04_P023" (solid, pour order 23): 43.1,2.15 42.8,1.85 42.8,0.85 43.1,0.55 45.3,0.55 45.3,2.15
GND on L4 [BOTTOM] "GND_L04_P019" (solid, pour order 19): 38.5,8.6 41.65,8.6 41.65,5.3 38.5,5.3
+5V on L4 [BOTTOM] "+5V_L04_P013" (solid, pour order 13): 3.09,15.741 3.25,16.028 3.25,16.59 3.25,16.681 3.25,17.25 3.75,17.75 5.25,17.75 5.5,18 5.5,19.1 5.25,19.35 1.2,19.35 1,19.15 1,16.25 1.509,15.741
+3V3 on L3[PWR] "+3V3_L03_P020" (solid, pour order 20): -0.05,30 -0.05,-0.05 65.05,-0.05 65.05,30
+5V on L3[PWR] "+5V_L03_P015" (solid, pour order 15): 3.45,18.25 3.45,15.9 5.5,13.85 5.5,8.25 9.75,4 46.5,4 49.7,7.2 49.7,19.45 52.25,22 56.25,22 56.5,22 57.5,21 57.5,17 59.25,15.25 63.5,15.25 64.75,14 64.75,8.75 64.75,0 0,0 0,18.25
+5V_IN on L3[PWR] "+5V_IN_L03_P009" (solid, pour order 9): 11.75,29.85 11.7,29.8 -0.05,29.8 -0.05,21.4 0.05,21.3 5.3,21.3 6.15,22.15 6.15,25.55 7.2,26.6 11.95,26.6 12.2,26.85 12.2,29.2
0V9 on L3[PWR] "0V9_L03_P010" (solid, pour order 10): 37.535,3.865 37.535,12.585 38.45,13.5 41.3,13.5 41.9,12.9 41.9,11.75 41.35,11.2 40,11.2 38.5,9.7 38.5,5.4 39,4.9 40.15,4.9 40.744,4.306 40.722,3.722 40.5,3.5 37.9,3.5
+1V8f on L3[PWR] "+1V8F_L03_P004" (solid, pour order 4): 24.8,5.65 25.4,5.65 25.75,5.3 25.75,4.384 25.5,4.134 19.566,4.134 18.75,4.95 18.35,4.95 18.05,4.65 18.05,3.95 18.4,3.6 20.546,3.6 21.471,2.675 26.625,2.675 27.1,3.15 27.1,5.9 26.404,6.596 24.48,6.596 24.48,5.97
5VVGA on L3[PWR] "5VVGA_L03_P005" (solid, pour order 5): 36.25,5.4 35.53,4.68 35.53,3.995 35.69,3.835 36.985,3.835 37.249,4.099 37.249,6.813 36.962,7.101 36.452,7.101 36.25,6.9
5VVGA on L1 [TOP] "5VVGA_L01_P038" (solid, pour order 38): 34.053,4.3 36.785,4.3 37.22,3.865 38.235,3.865 38.5,3.6 38.5,3.3 38.8,3 39,3 39.1,2.9 39.1,2.35 39.05,2.3 36.7,2.3 36.3,2.7 34.1,2.7 33.9,2.9 33.9,4.147
+2V5 on L1 [TOP] "+2V5_L01_P037" (solid, pour order 37): 24.411,20.639 24.25,20.799 24.25,22.849 24.389,22.988 24.797,23.4 26,23.4 26,20.65 25.75,20.4 24.651,20.4
+5V on L1 [TOP] "+5V_L01_P012" (solid, pour order 12): 36.35,2 34.1,2 33.85,1.75 33.85,0.65 34,0.5 36.35,0.5
GND on L2 [GND] "GND_L02_P000" (solid, pour order 0): -0.05,30 -0.05,-0.05 65.05,-0.05 65.05,30

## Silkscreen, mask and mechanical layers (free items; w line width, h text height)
Top Overlay:
  text "Pulser" at 48.15,22.15 h0.8
  text "DONE" at 35.1,19.9 h0.8
  text "ICS" at 35.1,17.9 h0.8
  text "HILO" at 35.1,16.05 h0.8
  text "PWR" at 35.14,14.2 h0.8
  text "VGA" at 35.55,12.375 h0.8
  text "USER" at 2.07,11.53 h1 r90
  text "DAC" at 29.39,11.21 h0.8
  text "FPGA" at 15.19,11.117 h0.8
  text "ADC" at 15.8,7.25 h0.8
  text "TRIG" at 2.07,6.93 h1 r90
  text "GND" at 12.1,5.8 h0.8
  text "+3V3" at 5.9,4.7 h0.8
  text "+5V" at 6.35,1.7 h0.8
Bottom Overlay:
  drawing of 5 lines, arcs and shapes, not listed
  text "lit3-32" at 39.246,20.504 h1.52
  text "un0rick.cc" at 41.496,18.004 h1.52
  text "O" at 9,3.25 h15
  text "FR000016" at 15.6,0.65 h0.95
M2_BoardOutline:
  lines w0.254: 0,27 cw(c3,27) 3,30 ; 0,27 0,27 ; 0,27 0,3 ccw(c3,3) 3,0 ; 3,0 3,0 ; 3,0 62,0 ccw(c62,3) 65,3 ; 3,30 62,30 cw(c62,27) 65,27 65,3 ; 3,30 3,30 ; 65,3 65,3
M5_StackDetails:
  drawing of 453 lines, arcs and shapes, not listed
  text "Layer" at -21.908,126.177 h1.52
  text "Name" at -11.497,126.177 h1.52
  text "Material" at 12.119,126.177 h1.52
  text "Thickness" at 33.957,126.177 h1.52
  text "Constant" at 50.463,126.177 h1.52
  text "Board Layer Stack" at 64.937,126.177 h1.52
  text "Top Overlay" at -11.497,123.129 h1.52
  text "Top Solder" at -11.497,120.081 h1.52
  text "Solder Resist" at 12.119,120.081 h1.52
  text "0.40mil" at 33.957,120.081 h1.52
  text "3.5" at 50.463,120.081 h1.52
  text "1" at -21.908,117.033 h1.52
  text "L1 [TOP]" at -11.497,117.033 h1.52
  text "1.38mil" at 33.957,117.033 h1.52
  text "Dielectric 2" at -11.497,113.985 h1.52
  text "PP-018" at 12.119,113.985 h1.52
  text "4.33mil" at 33.957,113.985 h1.52
  text "4.29" at 50.463,113.985 h1.52
  text "2" at -21.908,110.937 h1.52
  text "L2 [GND]" at -11.497,110.937 h1.52
  text "]" at 12.119,110.937 h1.52
  text "1.38mil" at 33.957,110.937 h1.52
  text "Dielectric 1" at -11.497,107.889 h1.52
  text "FR-4" at 12.119,107.889 h1.52
  text "44.49mil" at 33.957,107.889 h1.52
  text "3.96" at 50.463,107.889 h1.52
  text "3" at -21.908,104.841 h1.52
  text "L3[PWR]" at -11.497,104.841 h1.52
  text "]" at 12.119,104.841 h1.52
  text "1.38mil" at 33.957,104.841 h1.52
  text "Dielectric 3" at -11.497,101.793 h1.52
  text "PP-018" at 12.119,101.793 h1.52
  text "4.33mil" at 33.957,101.793 h1.52
  text "4.29" at 50.463,101.793 h1.52
  text "4" at -21.908,98.745 h1.52
  text "L4 [BOTTOM]" at -11.497,98.745 h1.52
  text "1.38mil" at 33.957,98.745 h1.52
  text "Bottom Solder" at -11.497,95.697 h1.52
  text "Solder Resist" at 12.119,95.697 h1.52
  text "0.40mil" at 33.957,95.697 h1.52
  text "3.5" at 50.463,95.697 h1.52
  text "Bottom Overlay" at -11.497,92.649 h1.52
M6_FabNotes:
  text "Files" at 115.3,131.35 h1.52
  text "*.GTO - Top Overlay" at 115.3,128.85 h1.52
  text "*.GTP - Top Paste" at 115.3,126.35 h1.52
  text "*.GTS - Top Solder" at 115.3,123.85 h1.52
  text "*.GTL - L1 (Positive)" at 115.3,121.35 h1.52
  text "*.G1  - L2 (Positive)" at 115.3,118.85 h1.52
  text "*.G2  - L3 (Positive)" at 115.3,116.35 h1.52
  text "*.GBL - L4 (Positive)" at 115.3,113.85 h1.52
  text "*.GBS - Bottom Solder" at 115.3,111.35 h1.52
  text "*.GBP - Bottom Paste" at 115.3,108.85 h1.52
  text "*.GBO - Bottom Overlay" at 115.3,106.35 h1.52
  text "*.GM2 - Board outline" at 115.3,103.85 h1.52
  text "*.GM5 - Stackup Details" at 115.3,101.35 h1.52
  text "*.GM6 - Fab Notes" at 115.3,98.85 h1.52
  text "*.GM11 - Mechanical dimensions" at 115.3,96.35 h1.52
  text "Board info" at 117.3,79.75 h1.52
  text "Minimum Spacing >0.152mm" at 117.3,74.75 h1.52
  text "Minimum Track >0.152mm" at 117.3,72.25 h1.52
  text "Minimum Through Hole VIA: 0.5mm (pad) / 0.2mm (drill). Drilling: L1-L4" at 117.3,70.15 h1.52
  text "1. REMOVE ALL NON-FUNCTIONAL INNER LAYER PADS." at 117.3,65.15 h1.52
  text "2. FINISHED PANEL THICKNESS IS NOT CRITICAL: TO BE APPROXIMATELY 1.6mm" at 117.25,60.45 h1.52
  text "3. BOARD FINISH: IMMERSION Au/ELECTROLESS Ni; 0.05-0.12 um GOLD; 3-6um NICKEL" at 117.25,55.45 h1.52
  text "4. OLDER RESIST: APPLY TO BOTH SIDES COLOUR - Red" at 117.25,50.45 h1.52
  text "5. COMPONENT IDENT: COLOUR TO BE WHITE" at 117.25,45.45 h1.52
Drill Drawing:
  circle w0.254: c-92.187,155.749 r0.508
  circle w0.254: c-92.187,155.749 r0.847
  lines w0.254: -93.034,147.282 -92.187,147.705 -91.341,147.282 -91.764,148.129 -91.341,148.975 -92.187,148.552 -93.034,148.975 -92.611,148.129 -93.034,147.282 ; -93.034,151.092 -91.341,151.092 -91.341,152.785 -93.034,152.785 -93.034,151.092 ; -93.034,160.405 -91.341,160.405 -92.187,158.712 -93.034,160.405
  lines w0.381: -94.553,146.139 174.206,146.139 ; -94.553,161.379 174.206,161.379 ; -80.56,142.329 -80.56,165.189 ; -65.324,142.329 -65.324,165.189 ; -36.377,142.329 -36.377,165.189 ; -23.528,142.329 -23.528,165.189 ; -4.889,142.329 -4.889,165.189 ; 29.391,142.329 29.391,165.189 ; 44.373,142.329 44.373,165.189 ; 63.316,142.329 63.316,165.189 ; 83.631,142.329 83.631,165.189 ; 105.316,142.329 105.316,165.189 ; 139.19,142.329 139.19,165.189 ; -94.553,142.329 174.206,142.329 174.206,165.189 -94.553,165.189 -94.553,142.329
  text "Symbol" at -92.267,162.522 h1.83
  text "Count" at -79.417,162.522 h1.83
  text "Hole Size" at -64.181,162.522 h1.83
  text "Plated" at -35.234,162.522 h1.83
  text "Hole Type" at -22.385,162.522 h1.83
  text "Drill Layer Pair" at -3.746,162.522 h1.83
  text "Via/Pad" at 30.534,162.522 h1.83
  text "Pad Shape" at 45.516,162.522 h1.83
  text "Template" at 64.459,162.522 h1.83
  text "Description" at 84.774,162.522 h1.83
  text "Hole Tolerance (+)" at 106.459,162.522 h1.83
  text "Hole Tolerance (-)" at 140.333,162.522 h1.83
  text "1" at -79.417,158.712 h1.52
  text "0.750mm (29.53mil)" at -64.181,158.712 h1.52
  text "PTH" at -35.234,158.712 h1.52
  text "Round" at -22.385,158.712 h1.52
  text "L1 [TOP] - L4 [BOTTOM]" at -3.746,158.712 h1.52
  text "Pad" at 30.534,158.712 h1.52
  text "Rounded" at 45.516,158.712 h1.52
  text "c150h75m0mx0" at 64.459,158.712 h1.52
  text "4" at -79.417,154.902 h1.52
  text "2.800mm (110.24mil)" at -64.181,154.902 h1.52
  text "NPTH" at -35.234,154.902 h1.52
  text "Round" at -22.385,154.902 h1.52
  text "L1 [TOP] - L4 [BOTTOM]" at -3.746,154.902 h1.52
  text "Pad" at 30.534,154.902 h1.52
  text "Rounded" at 45.516,154.902 h1.52
  text "c0hn280m180" at 64.459,154.902 h1.52
  text "44" at -79.417,151.092 h1.52
  text "0.900mm (35.43mil)" at -64.181,151.092 h1.52
  text "PTH" at -35.234,151.092 h1.52
  text "Round" at -22.385,151.092 h1.52
  text "L1 [TOP] - L4 [BOTTOM]" at -3.746,151.092 h1.52
  text "Pad" at 30.534,151.092 h1.52
  text "(Mixed)" at 45.516,151.092 h1.52
  text "(Mixed)" at 64.459,151.092 h1.52
  text "226" at -79.417,147.282 h1.52
  text "0.200mm (7.87mil)" at -64.181,147.282 h1.52
  text "PTH" at -35.234,147.282 h1.52
  text "Round" at -22.385,147.282 h1.52
  text "L1 [TOP] - L4 [BOTTOM]" at -3.746,147.282 h1.52
  text "Via" at 30.534,147.282 h1.52
  text "Rounded" at 45.516,147.282 h1.52
  text "v50h20m0mx0" at 64.459,147.282 h1.52
  text "275 Total" at -79.417,143.472 h1.52

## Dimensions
0,0 to 3,30 on Top Dimensions
0,0 to 65,3 on Top Dimensions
